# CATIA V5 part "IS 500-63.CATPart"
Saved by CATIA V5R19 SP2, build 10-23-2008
Part number: IS 500-63
Bounding box of the stored display mesh (mm): x -22.494 to 22.494, y -22.494 to 22.494, z 0 to 212
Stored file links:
  C:\Users\Bora\Desktop\3D Katı model\IS serisi\IS 500\IS 500-63.CATPart
  C:\Program Files\Dassault Systemes\B19\intel_a\reffiles\standard\MetricThickPitch.txt
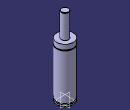
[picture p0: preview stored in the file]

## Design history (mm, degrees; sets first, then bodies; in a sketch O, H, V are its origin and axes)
Body1 (main body)
  Sketch1 on yz-plane, origin (0, 0, 0), H (0, 1, 0), V (0, 0, 1)
    point P3 (10, 211)
    point P5 (10, 211)
    point P7 (22.5, 133.5)
    point P8 (22.5, 131.5)
    point P12 (22.5, 131.5)
    point P13 (22.5, 133.5)
    line L1 (22.5, 0) -> (22.5, 4)
    line L2 (10, 211) -> (10, 147)
    arc A1 centre (9, 211) radius 1 from (10, 211) to (9, 212) ccw
    arc A2 centre (22.5, 132.5) radius 1 from (22.5, 133.5) to (22.5, 131.5) ccw
    line L3 (20, 7.5) -> (20, 4)
    line L4 (22.5, 7.5) -> (22.5, 131.5)
    line L5 (22.5, 133.5) -> (22.5, 147)
    line L6 (0, 0) -> (22.5, 0)
    line L7 (20, 4) -> (22.5, 4)
    line L8 (20, 7.5) -> (22.5, 7.5)
    line L9 (10, 147) -> (22.5, 147)
    line L10 (9, 212) -> (0, 212)
    point P15 (0, 212)
    horizontal: L6 H, L7 H, L8 H, L9 H
    coincidence: P15 V, P3 P5, P7 P13, P8 P12
    tangency: L10 A1
  Shaft1: profile Sketch1, axis Sketch1.V, angle 360
  Sketch2 on face of Shaft1 from Sketch1.L6, origin (0, 0, 0), H (1, 0, 0), V (0, -1, 0)
    point P1 (10, 0)
    distance P1 V = 10
  Hole1: placed by Sketch2, at (10, 0, 0) direction (0, 0, 1), diameter 6.647, depth 13, threaded "M8", thread diameter 8, thread depth 13, pitch 1.25
  Sketch3 on face of Shaft1 from Sketch1.L6, origin (0, 0, 0), H (1, 0, 0), V (0, -1, 0)
    point P1 (-10, 0)
    distance P1 V = 10
  Hole2: placed by Sketch3, at (-10, 0, 0) direction (0, 0, 1), diameter 6.647, depth 13, threaded "M8", thread diameter 8, thread depth 13, pitch 1.25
